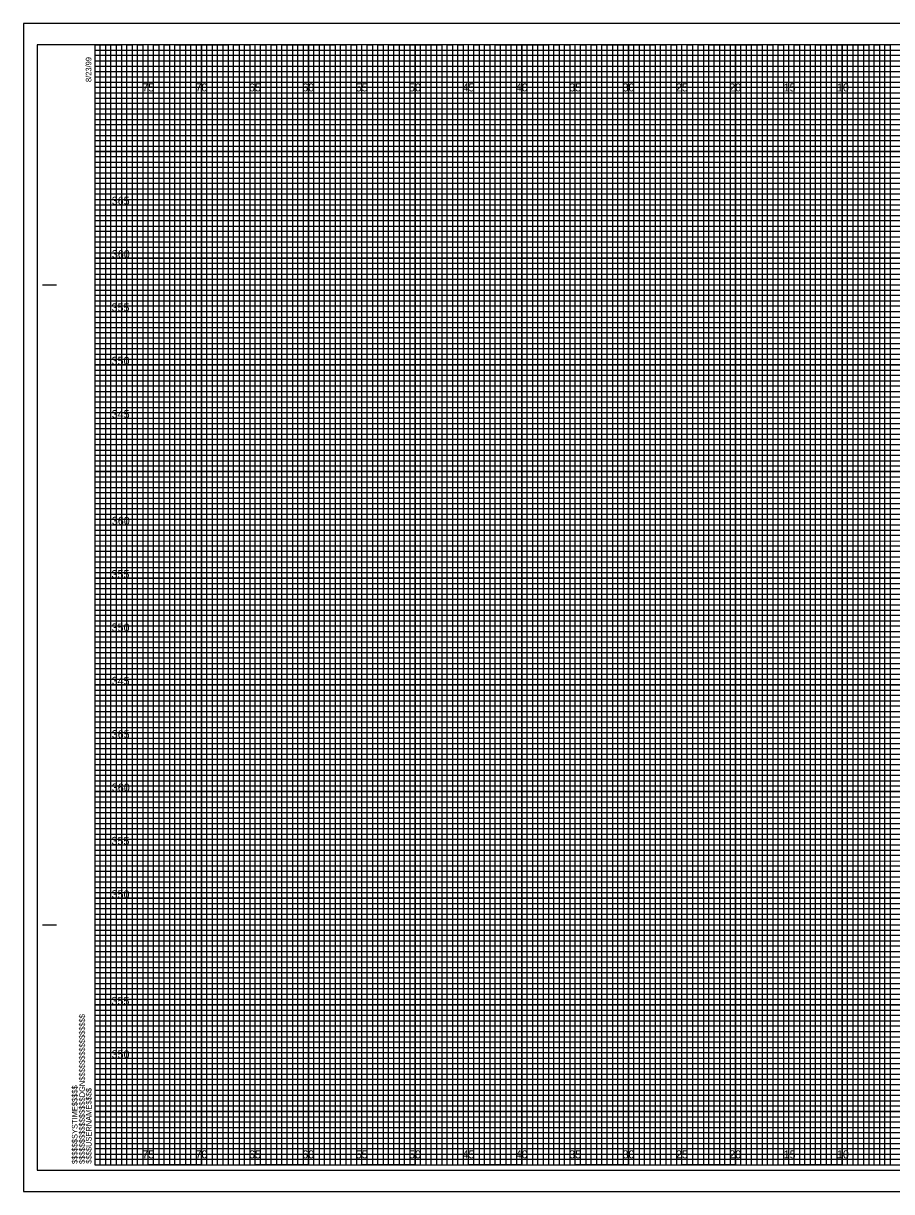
# Model space of a CAD drawing. Extents: x -7 to 266, y -5 to 437.
# Drawn here: x -6.7 to 74.6, y -2.5 to 107 of the extents above; entities that cross this region are included whole.
import ezdxf

# ---------------------------------------------------------------- set-up
doc = ezdxf.new("R2010")
doc.units = 0
for name, color, linetype in [('Exist XS Center Line Elevation Label', 7, 'Continuous'), ('Exist XS Ground Line', 7, 'Continuous'), ('Prop XS Finish Grade', 7, 'Continuous'), ('Prop XS Finish Grade Concrete', 7, 'Continuous'), ('Prop XS Finish Grade Earthwork', 7, 'Continuous'), ('Prop XS Hydro Elevations', 7, 'Continuous'), ('Prop XS Pvmt Edge Slope', 7, 'Continuous'), ('Prop XS SE Text', 7, 'Continuous'), ('Prop XS SS Elevation Text', 7, 'Continuous'), ('Prop XS Subgrade Earthwork', 7, 'Continuous'), ('Typical Guardrail CELL', 7, 'Continuous')]:
    doc.layers.add(name, color=color, linetype=linetype)

msp = doc.modelspace()

# ---------------------------------------------------------------- linework, layer by layer
at = {"layer": 'Exist XS Center Line Elevation Label'}
for points in [[(0, 105), (2.5, 105), (2.5, 0), (7.5, 0), (7.5, 105), (12.5, 105), (12.5, 0), (17.5, 0), (17.5, 105), (22.5, 105), (22.5, 0), (27.5, 0), (27.5, 105), (32.5, 105), (32.5, 0), (37.5, 0), (37.5, 105), (42.5, 105), (42.5, 0), (47.5, 0), (47.5, 105), (52.5, 105), (52.5, 0), (57.5, 0), (57.5, 105), (62.5, 105), (62.5, 0), (67.5, 0), (67.5, 105), (72.5, 105), (72.5, 0), (77.5, 0)], [(0, 102.5), (137.5, 102.5)], [(0, 92.5), (160, 92.5), (160, 97.5), (0, 97.5)], [(0, 82.5), (160, 82.5), (160, 87.5), (0, 87.5)], [(0, 72.5), (160, 72.5), (160, 77.5), (0, 77.5)], [(0, 62.5), (160, 62.5), (160, 67.5), (0, 67.5)], [(0, 52.5), (160, 52.5), (160, 57.5), (0, 57.5)], [(0, 42.5), (160, 42.5), (160, 47.5), (0, 47.5)], [(0, 32.5), (160, 32.5), (160, 37.5), (0, 37.5)], [(0, 22.5), (160, 22.5), (160, 27.5), (0, 27.5)], [(0, 12.5), (160, 12.5), (160, 17.5), (0, 17.5)], [(0, 2.5), (160, 2.5), (160, 7.5), (0, 7.5)]]:
    msp.add_lwpolyline(points, dxfattribs=at)
at = {"layer": 'Exist XS Ground Line'}
for p, q in [((5, 105), (0, 105)), ((5, 0), (5, 105)), ((15, 105), (10, 105)), ((10, 105), (10, 0)), ((15, 0), (15, 105)), ((25, 105), (20, 105)), ((20, 105), (20, 0)), ((25, 0), (25, 105)), ((35, 105), (30, 105)), ((30, 105), (30, 0)), ((35, 0), (35, 105)), ((45, 105), (40, 105)), ((40, 105), (40, 0)), ((45, 0), (45, 105)), ((55, 105), (50, 105)), ((50, 105), (50, 0)), ((55, 0), (55, 105)), ((65, 105), (60, 105)), ((60, 105), (60, 0)), ((65, 0), (65, 105)), ((75, 105), (70, 105)), ((70, 105), (70, 0)), ((10, 0), (5, 0)), ((20, 0), (15, 0)), ((30, 0), (25, 0)), ((40, 0), (35, 0)), ((50, 0), (45, 0)), ((60, 0), (55, 0)), ((70, 0), (65, 0))]:
    msp.add_line(p, q, dxfattribs=at)
for points in [[(0, 100), (160, 100), (160, 95), (0, 95)], [(0, 90), (160, 90), (160, 85), (0, 85)], [(0, 80), (160, 80), (160, 75), (0, 75)], [(0, 70), (160, 70), (160, 65), (0, 65)], [(0, 60), (160, 60), (160, 55), (0, 55)], [(0, 50), (160, 50), (160, 45), (0, 45)], [(0, 40), (160, 40), (160, 35), (0, 35)], [(0, 30), (160, 30), (160, 25), (0, 25)], [(0, 20), (160, 20), (160, 15), (0, 15)], [(0, 10), (160, 10), (160, 5), (0, 5)]]:
    msp.add_lwpolyline(points, dxfattribs=at)
at = {"layer": 'Prop XS Finish Grade'}
for p, q in [((5, 0), (5, 105)), ((10, 0), (10, 105)), ((15, 0), (15, 105)), ((20, 0), (20, 105)), ((25, 0), (25, 105)), ((30, 0), (30, 105)), ((35, 0), (35, 105)), ((40, 0), (40, 105)), ((45, 0), (45, 105)), ((50, 0), (50, 105)), ((55, 0), (55, 105)), ((60, 0), (60, 105)), ((65, 0), (65, 105)), ((70, 0), (70, 105)), ((0, 100), (160, 100)), ((0, 95), (160, 95)), ((0, 90), (160, 90)), ((0, 85), (160, 85)), ((0, 80), (160, 80)), ((0, 75), (160, 75)), ((0, 70), (160, 70)), ((0, 65), (160, 65)), ((0, 60), (160, 60)), ((0, 55), (160, 55)), ((0, 50), (160, 50)), ((0, 45), (160, 45)), ((0, 40), (160, 40)), ((0, 35), (160, 35)), ((0, 30), (160, 30)), ((0, 25), (160, 25)), ((0, 20), (160, 20)), ((0, 15), (160, 15)), ((0, 10), (160, 10)), ((0, 5), (160, 5))]:
    msp.add_line(p, q, dxfattribs=at)
at = {"layer": 'Prop XS Finish Grade Earthwork'}
msp.add_lwpolyline([(-6.7, -2.5), (161.65, -2.5), (161.65, 107), (-6.7, 107)], close=True, dxfattribs=at)
at = {"layer": 'Prop XS Hydro Elevations'}
for p, q in [((-4.9, 82.5), (-3.65, 82.5)), ((-4.85, 82.5), (-3.6, 82.5)), ((-4.9, 22.5), (-3.65, 22.5)), ((-4.85, 22.5), (-3.6, 22.5)), ((0, 0), (0, 0)), ((0, 0), (0, 0)), ((0, 0), (0, 0)), ((0, 0), (0, 0)), ((0, 0), (0, 0)), ((0, 0), (0, 0)), ((0, 0), (0, 0))]:
    msp.add_line(p, q, dxfattribs=at)
msp.add_lwpolyline([(160, 105), (0, 105), (0, 0), (160, 0)], close=True, dxfattribs=at)
at = {"layer": 'Prop XS Pvmt Edge Slope'}
msp.add_lwpolyline([(-5.4, -0.5), (161.2, -0.5), (161.2, 105), (-5.4, 105)], close=True, dxfattribs=at)
at = {"layer": 'Prop XS SE Text'}
for p, q in [((0, 104.5), (130, 104.5)), ((130, 103.99), (0, 103.99)), ((0, 103.99), (0, 103.5)), ((0, 103.5), (130, 103.5)), ((130, 102.95), (0, 102.95)), ((0, 102.95), (0, 102)), ((0, 102), (160, 102))]:
    msp.add_line(p, q, dxfattribs=at)
for points in [[(0, 101.5), (135, 101.5), (160, 101.5), (160, 101), (0, 101)], [(0, 100.5), (160, 100.5), (160, 99.5), (0, 99.5)], [(0, 99), (160, 99), (160, 98.5), (0, 98.49)], [(0, 98), (160, 98), (160, 97), (0, 97)], [(0, 96.5), (160, 96.5), (160, 96), (0, 96)], [(0, 95.5), (160, 95.5), (160, 94.5), (0, 94.5)], [(0, 94), (160, 94), (160, 93.5), (0, 93.5)], [(0, 93), (160, 93), (160, 92), (0, 92)], [(0, 91.5), (160, 91.5), (160, 91), (0, 91)], [(0, 90.5), (160, 90.5), (160, 89.5), (0, 89.5)], [(0, 89), (160, 89), (160, 88.5), (0, 88.5)], [(0, 88), (160, 88), (160, 86.98), (160, 86.5), (160, 86), (0, 86)], [(0, 87), (160, 87), (160, 86.5), (0, 86.5)], [(0, 85.5), (160, 85.5), (160, 84.5), (0, 84.52)], [(0, 84.52), (160, 84.5), (160, 84), (0, 84)], [(0, 83.5), (160, 83.5), (160, 83), (0, 83)], [(0, 82), (160, 82), (160, 81.5), (0, 81.5)], [(0, 81), (160, 81), (160, 80.5), (0, 80.5)], [(-0.04, 79.45), (160, 79.45), (160, 78.94), (-0.04, 78.94)], [(0, 78.5), (160, 78.5), (160, 78), (0, 78)], [(0, 77), (160, 77), (160, 76.5), (0, 76.5)], [(0, 76), (160, 76), (160, 75.5), (0, 75.5)], [(0, 74.5), (160, 74.5), (160, 74), (0, 74)], [(0, 73.5), (160, 73.5), (160, 73), (0, 73)], [(0, 72), (160, 72), (160, 71.5), (0, 71.5)], [(0, 71), (160, 71), (160, 70.5), (0, 70.5)], [(0, 69.5), (160, 69.5), (160, 68.99), (0, 69)], [(0, 68.5), (160, 68.5), (160, 68), (0, 68)], [(0, 67), (160, 67), (160, 66.5), (0, 66.5)], [(0, 66), (160, 66), (160, 65.5), (0, 65.5)], [(0, 64.5), (160, 64.5), (160, 64), (0, 64)], [(0, 63.5), (160, 63.5), (160, 63), (0, 63)], [(0, 62), (160, 62), (160, 61.5), (0, 61.5)], [(0, 61), (160, 61), (160, 60.5), (0, 60.5)], [(0, 59.5), (160, 59.5), (160, 59), (0, 59)], [(0, 58.5), (160.03, 58.45), (160, 58), (0, 58)], [(0, 57), (160, 57), (160, 56.5), (0, 56.5)], [(0, 56), (160, 56), (160, 55.5), (0, 55.5)], [(0, 54.5), (160, 54.5), (160, 54), (0, 54)], [(0, 53.5), (160, 53.5), (160, 53), (0, 53)], [(0, 52), (160, 52), (160, 51.5), (0, 51.5)], [(0, 51), (160, 51), (160, 50.5), (0, 50.5)], [(0, 49.5), (160, 49.5), (160, 49), (0, 49)], [(0, 48.5), (160, 48.5), (160, 48), (0, 48)], [(0, 47), (160, 47), (160, 46.5), (0, 46.5)], [(0, 46), (160, 46), (160, 45.5), (0, 45.5)], [(0, 44.5), (160, 44.5), (160, 44), (0, 44)], [(0, 43.5), (160, 43.5), (160, 43), (0, 43)], [(0, 42), (160, 42), (160, 41.5), (0, 41.5)], [(0, 41), (160, 41), (160, 40.5), (0, 40.5)], [(0, 39.5), (160, 39.5), (160, 38.99), (0, 39)], [(0, 38.5), (160, 38.5), (160, 38), (0, 38)], [(0, 37), (160, 37), (160, 36.5), (0, 36.5)], [(0, 36), (160, 36), (160, 35.5), (0, 35.5)], [(0, 34.5), (160, 34.5), (160, 34), (0, 34)], [(0, 33.5), (160, 33.5), (160, 33), (0, 33)], [(0, 32), (160, 32), (160, 31.5), (0, 31.5)], [(0, 31), (160, 31), (160, 30.5), (0, 30.5)], [(0, 29.5), (160, 29.5), (160, 29), (0, 29)], [(0, 28.5), (160.03, 28.46), (160, 28), (0, 28)], [(0, 27), (160, 27), (160, 26.5), (0, 26.5)], [(0, 26), (160, 26), (160, 25.5), (0, 25.5)], [(0, 24.5), (160, 24.5), (160, 24), (0, 24)], [(0, 23.5), (160, 23.5), (160, 23), (0, 23)], [(0, 22), (160, 22), (160, 21.5), (0, 21.5)], [(0, 21), (160, 21), (160, 20.5), (0, 20.5)], [(0, 19.5), (160, 19.5), (160, 19), (0, 19)], [(0, 18.5), (160, 18.5), (160, 18), (0, 18)], [(0, 17), (160, 17), (160, 16.5), (0, 16.5)], [(0, 16), (160, 16), (160, 15.5), (0, 15.5)], [(0, 14.5), (160, 14.5), (160, 14), (0, 14)], [(0, 13.5), (160, 13.5), (160, 13), (0, 13)], [(0, 12), (160, 12), (160, 11.5), (0, 11.5)], [(0, 11), (160, 11), (160, 10.5), (0, 10.5)], [(0, 9.5), (160, 9.5), (160, 9), (0, 9)], [(0, 8.5), (160, 8.5), (160, 8), (0, 8)], [(0, 7), (160, 7), (160, 6.5), (0, 6.5)], [(0, 6), (160, 6), (160, 5.5), (0, 5.5)], [(0, 4.5), (160, 4.5), (160, 4), (0, 4)], [(0, 3.5), (160, 3.5), (160, 3), (0, 3)], [(0, 2), (160, 2), (160, 1.5), (0, 1.5)], [(0, 1), (160, 1), (160, 0.5), (0, 0.5)]]:
    msp.add_lwpolyline(points, dxfattribs=at)
at = {"layer": 'Prop XS SS Elevation Text'}
for points in [[(0, 0), (0.5, 0), (0.5, 105), (1, 105), (1, 0)], [(1, 0), (1.5, 0), (1.5, 105), (2, 105), (2, 0)], [(2.5, 0), (3, 0), (3, 105), (3.5, 105), (3.5, 0)], [(3.5, 0), (4, 0), (4, 105), (4.5, 105), (4.5, 0)], [(5, 0), (5.5, 0), (5.5, 105), (6, 105), (6, 0)], [(6, 0), (6.5, 0), (6.5, 105), (7, 105), (7, 0)], [(7.5, 0), (8, 0), (8, 105), (8.5, 105), (8.5, 0)], [(8.5, 0), (9, 0), (9, 105), (9.5, 105), (9.5, 0)], [(10, 0), (10.5, 0), (10.5, 105), (11, 105), (11, 0)], [(11, 0), (11.5, 0), (11.5, 105), (12, 105), (12, 0)], [(12.5, 0), (13, 0), (13, 105), (13.5, 105), (13.5, 0)], [(13.5, 0), (14, 0), (14, 105), (14.5, 105), (14.5, 0)], [(15, 0), (15.5, 0), (15.5, 105), (16, 105), (16, 0)], [(16, 0), (16.5, 0), (16.5, 105), (17, 105), (17, 0)], [(17.5, 0), (18, 0), (18, 105), (18.5, 105), (18.5, 0)], [(18.5, 0), (19, 0), (19, 105), (19.5, 105), (19.5, 0)], [(20, 0), (20.5, 0), (20.5, 105), (21, 105), (21, 0)], [(21, 0), (21.5, 0), (21.5, 105), (22, 105), (22, 0)], [(22.5, 0), (23, 0), (23, 105), (23.5, 105), (23.5, 0)], [(23.5, 0), (24, 0), (24, 105), (24.5, 105), (24.5, 0)], [(25, 0), (25.5, 0), (25.5, 105), (26, 105), (26, 0)], [(26, 0), (26.5, 0), (26.5, 105), (27, 105), (27, 0)], [(27.5, 0), (28, 0), (28, 105), (28.5, 105), (28.5, 0)], [(28.5, 0), (29, 0), (29, 105), (29.5, 105), (29.5, 0)], [(30, 0), (30.5, 0), (30.5, 105), (31, 105), (31, 0)], [(31, 0), (31.5, 0), (31.5, 105), (32, 105), (32, 0)], [(32.5, 0), (33, 0), (33, 105), (33.5, 105), (33.5, 0)], [(33.5, 0), (34, 0), (34, 105), (34.5, 105), (34.5, 0)], [(35, 0), (35.5, 0), (35.5, 105), (36, 105), (36, 0)], [(36, 0), (36.5, 0), (36.5, 105), (37, 105), (37, 0)], [(37.5, 0), (38, 0), (38, 105), (38.5, 105), (38.5, 0)], [(38.5, 0), (39, 0), (39, 105), (39.5, 105), (39.5, 0)], [(40, 0), (40.5, 0), (40.5, 105), (41, 105), (41, 0)], [(41, 0), (41.5, 0), (41.5, 105), (42, 105), (42, 0)], [(42.5, 0), (43, 0), (43, 105), (43.5, 105), (43.5, 0)], [(43.5, 0), (44, 0), (44, 105), (44.5, 105), (44.5, 0)], [(45, 0), (45.5, 0), (45.5, 105), (46, 105), (46, 0)], [(46, 0), (46.5, 0), (46.5, 105), (47, 105), (47, 0)], [(47.5, 0), (48, 0), (48, 105), (48.5, 105), (48.5, 0)], [(48.5, 0), (49, 0), (49, 105), (49.5, 105), (49.5, 0)], [(50, 0), (50.5, 0), (50.5, 105), (51, 105), (51, 0)], [(51, 0), (51.5, 0), (51.5, 105), (52, 105), (52, 0)], [(52.5, 0), (53, 0), (53, 105), (53.5, 105), (53.5, 0)], [(53.5, 0), (54, 0), (54, 105), (54.5, 105), (54.5, 0)], [(55, 0), (55.5, 0), (55.5, 105), (56, 105), (56, 0)], [(56, 0), (56.5, 0), (56.5, 105), (57, 105), (57, 0)], [(57.5, 0), (58, 0), (58, 105), (58.5, 105), (58.5, 0)], [(58.5, 0), (59, 0), (59, 105), (59.5, 105), (59.5, 0)], [(60, 0), (60.5, 0), (60.5, 105), (61, 105), (61, 0)], [(61, 0), (61.5, 0), (61.5, 105), (62, 105), (62, 0)], [(62.5, 0), (63, 0), (63, 105), (63.5, 105), (63.5, 0)], [(63.5, 0), (64, 0), (64, 105), (64.5, 105), (64.5, 0)], [(65, 0), (65.5, 0), (65.5, 105), (66, 105), (66, 0)], [(66, 0), (66.5, 0), (66.5, 105), (67, 105), (67, 0)], [(67.5, 0), (68, 0), (68, 105), (68.5, 105), (68.5, 0)], [(68.5, 0), (69, 0), (69, 105), (69.5, 105), (69.5, 0)], [(70, 0), (70.5, 0), (70.5, 105), (71, 105), (71, 0)], [(71, 0), (71.5, 0), (71.5, 105), (72, 105), (72, 0)], [(72.5, 0), (73, 0), (73, 105), (73.5, 105), (73.5, 0)], [(73.5, 0), (74, 0), (74, 105), (74.5, 105), (74.5, 0)]]:
    msp.add_lwpolyline(points, dxfattribs=at)
at = {"layer": 'Prop XS Subgrade Earthwork'}
for p, q in [((161.65, 107), (-6.7, 107)), ((-6.7, 107), (-6.7, -2.5)), ((-6.7, -2.5), (161.65, -2.5))]:
    msp.add_line(p, q, dxfattribs=at)

# ---------------------------------------------------------------- texts
at = {"layer": 'Prop XS Finish Grade Concrete'}
for s, p in [('365', (1.58, 90)), ('360', (1.59, 85)), ('355', (1.56, 80)), ('350', (1.57, 75)), ('345', (1.58, 70)), ('360', (1.59, 60)), ('355', (1.56, 55)), ('350', (1.57, 50)), ('345', (1.58, 45)), ('365', (1.58, 40)), ('360', (1.59, 35)), ('355', (1.56, 30)), ('350', (1.57, 25)), ('355', (1.56, 15)), ('350', (1.57, 10))]:
    msp.add_text(s, height=0.75, dxfattribs=at).set_placement(p)
at = {"layer": 'Prop XS Hydro Elevations'}
for s, p in [('8/23/99', (-0.33, 101.5)), ('$$$$$$$$$$$$$$$$DGN$$$$$$$$$$$$$$$$', (-0.94, 0.09)), ('$$$$$$SYSTIME$$$$$', (-1.63, 0.09)), ('$$$$USERNAME$$$$', (-0.31, 0.12))]:
    msp.add_text(s, height=0.525, rotation=90, dxfattribs=at).set_placement(p)
at = {"layer": 'Typical Guardrail CELL'}
for s, p in [('75', (4.44, 100.62)), ('70', (9.43, 100.62)), ('65', (14.44, 100.62)), ('60', (19.43, 100.62)), ('55', (24.44, 100.62)), ('50', (29.43, 100.62)), ('45', (34.44, 100.62)), ('40', (39.43, 100.62)), ('35', (44.44, 100.62)), ('30', (49.43, 100.62)), ('25', (54.44, 100.62)), ('20', (59.43, 100.62)), ('15', (64.53, 100.62)), ('10', (69.52, 100.62)), ('75', (4.44, 0.62)), ('70', (9.43, 0.62)), ('65', (14.44, 0.62)), ('60', (19.43, 0.62)), ('55', (24.44, 0.62)), ('50', (29.43, 0.62)), ('45', (34.44, 0.62)), ('40', (39.43, 0.62)), ('35', (44.44, 0.62)), ('30', (49.43, 0.62)), ('25', (54.44, 0.62)), ('20', (59.43, 0.62)), ('15', (64.53, 0.62)), ('10', (69.52, 0.62))]:
    msp.add_text(s, height=0.75, dxfattribs=at).set_placement(p)

doc.saveas('drawing.dxf')
